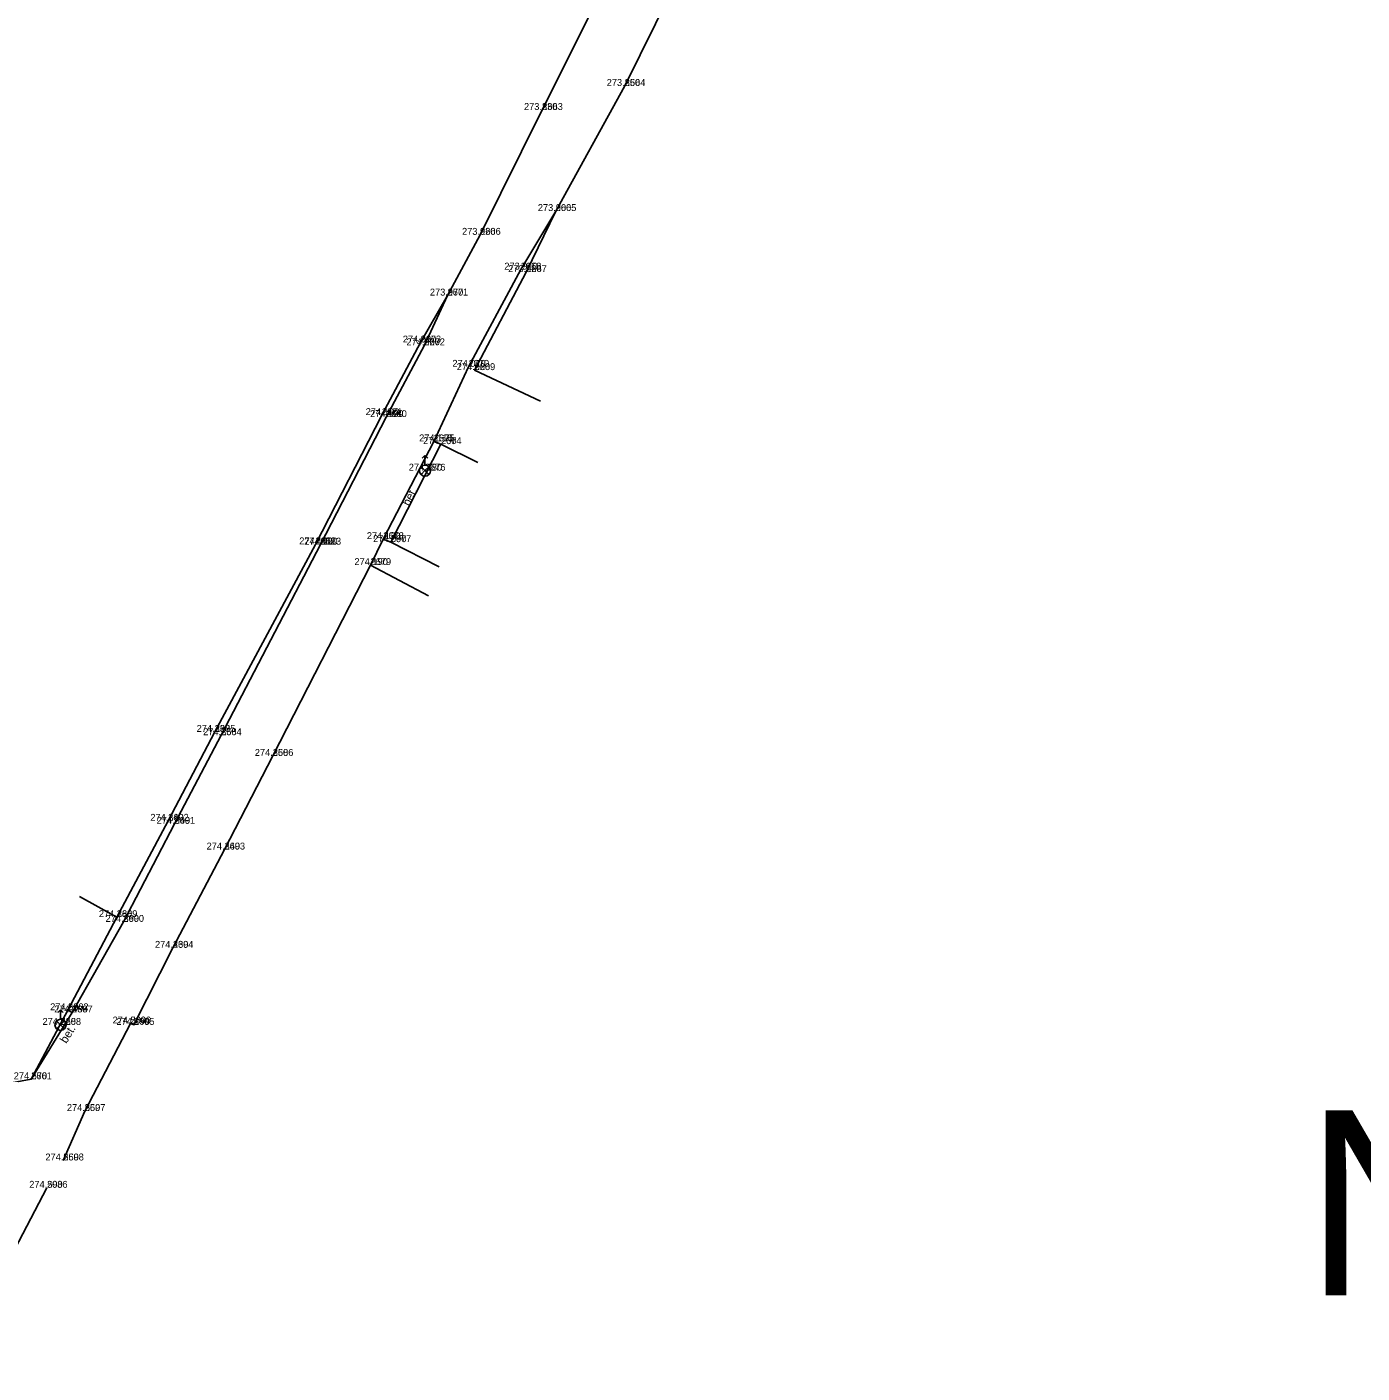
# Model space of a CAD drawing. Extents: x -776701 to -776081, y -974398 to -973771.
# Drawn here: x -776390.87 to -776342.51, y -974152.33 to -974103.58 of the extents above; entities that cross this region are included whole.
import ezdxf

# ---------------------------------------------------------------- set-up
doc = ezdxf.new("R2010")
doc.units = 0
for name, color, linetype in [('1 Body-bod', 7, 'Continuous'), ('10 Silnice-chodniky', 7, 'Continuous'), ('11 Rozhrani-nezpev zpev schody', 7, 'Continuous'), ('2 Body-cislo', 7, 'Continuous'), ('3 Body-vyska', 7, 'Continuous'), ('40 Popis-povrch', 7, 'Continuous'), ('58 Mobiliar', 7, 'Continuous'), ('7 Ploty', 7, 'Continuous'), ('Pop  PČ popisy', 7, 'Continuous')]:
    doc.layers.add(name, color=color, linetype=linetype)

msp = doc.modelspace()

# ---------------------------------------------------------------- linework, layer by layer
at = {"layer": '1 Body-bod'}
for p, q in [((-776369.21, -974105.72), (-776369.21, -974105.72)), ((-776372.2, -974106.59), (-776372.2, -974106.59)), ((-776371.71, -974110.25), (-776371.71, -974110.25)), ((-776374.45, -974111.11), (-776374.45, -974111.11)), ((-776372.98, -974112.37), (-776372.98, -974112.37)), ((-776372.78, -974112.46), (-776372.78, -974112.46)), ((-776375.63, -974113.31), (-776375.63, -974113.31)), ((-776376.61, -974115.01), (-776376.61, -974115.01)), ((-776376.47, -974115.11), (-776376.47, -974115.11)), ((-776374.87, -974115.89), (-776374.87, -974115.89)), ((-776374.65, -974116.01), (-776374.65, -974116.01)), ((-776378.01, -974117.64), (-776378.01, -974117.64)), ((-776377.85, -974117.71), (-776377.85, -974117.71)), ((-776376.13, -974118.59), (-776376.13, -974118.59)), ((-776375.87, -974118.69), (-776375.87, -974118.69)), ((-776376.45, -974119.65), (-776376.45, -974119.65)), ((-776380.42, -974122.32), (-776380.42, -974122.32)), ((-776380.23, -974122.33), (-776380.23, -974122.33)), ((-776377.96, -974122.13), (-776377.96, -974122.13)), ((-776377.69, -974122.24), (-776377.69, -974122.24)), ((-776378.42, -974123.07), (-776378.42, -974123.07)), ((-776384.06, -974129.11), (-776384.06, -974129.11)), ((-776383.83, -974129.23), (-776383.83, -974129.23)), ((-776381.96, -974129.98), (-776381.96, -974129.98)), ((-776385.75, -974132.33), (-776385.75, -974132.33)), ((-776385.52, -974132.44), (-776385.52, -974132.44)), ((-776383.71, -974133.37), (-776383.71, -974133.37)), ((-776387.61, -974135.82), (-776387.61, -974135.82)), ((-776387.37, -974135.99), (-776387.37, -974135.99)), ((-776385.58, -974136.93), (-776385.58, -974136.93)), ((-776389.38, -974139.19), (-776389.38, -974139.19)), ((-776389.23, -974139.27), (-776389.23, -974139.27)), ((-776389.65, -974139.72), (-776389.65, -974139.72)), ((-776387.12, -974139.67), (-776387.12, -974139.67)), ((-776386.99, -974139.72), (-776386.99, -974139.72)), ((-776390.71, -974141.69), (-776390.71, -974141.69)), ((-776388.77, -974142.84), (-776388.77, -974142.84)), ((-776389.55, -974144.63), (-776389.55, -974144.63)), ((-776390.14, -974145.62), (-776390.14, -974145.62))]:
    msp.add_line(p, q, dxfattribs=at)
at = {"layer": '10 Silnice-chodniky'}
for points in [[(-776371.71, -974110.25), (-776372.98, -974112.37), (-776374.87, -974115.89), (-776376.13, -974118.59), (-776377.96, -974122.13), (-776378.42, -974123.07)], [(-776375.63, -974113.31), (-776376.47, -974115.11), (-776377.85, -974117.71), (-776380.23, -974122.33), (-776383.83, -974129.23), (-776385.52, -974132.44)], [(-776375.87, -974118.69), (-776376.13, -974118.59)], [(-776377.69, -974122.24), (-776377.96, -974122.13)], [(-776390.71, -974141.69), (-776389.23, -974139.27), (-776387.37, -974135.99), (-776385.52, -974132.44)], [(-776389.38, -974139.19), (-776389.23, -974139.27)]]:
    msp.add_lwpolyline(points, dxfattribs=at)
at = {"layer": '11 Rozhrani-nezpev zpev schody'}
msp.add_lwpolyline([(-776392.71, -974139.472), (-776393.56, -974140.98), (-776391.75, -974141.88), (-776390.71, -974141.69), (-776389.38, -974139.19), (-776387.61, -974135.82), (-776388.963, -974135.076)], dxfattribs=at)
at = {"layer": '58 Mobiliar'}
for p, q in [((-776376.45, -974119.65), (-776376.593, -974119.508)), ((-776376.45, -974119.1), (-776376.55, -974119.2)), ((-776376.45, -974119.449), (-776376.45, -974119.1)), ((-776376.45, -974119.1), (-776376.35, -974119.2)), ((-776376.45, -974119.65), (-776376.307, -974119.508)), ((-776376.45, -974119.65), (-776376.593, -974119.792)), ((-776376.45, -974119.65), (-776376.45, -974119.65)), ((-776376.45, -974119.65), (-776376.307, -974119.792)), ((-776389.65, -974139.17), (-776389.75, -974139.27)), ((-776389.65, -974139.519), (-776389.65, -974139.17)), ((-776389.65, -974139.17), (-776389.55, -974139.27)), ((-776389.65, -974139.72), (-776389.792, -974139.578)), ((-776389.65, -974139.72), (-776389.792, -974139.863)), ((-776389.65, -974139.72), (-776389.508, -974139.578)), ((-776389.65, -974139.72), (-776389.65, -974139.72)), ((-776389.65, -974139.72), (-776389.508, -974139.863))]:
    msp.add_line(p, q, dxfattribs=at)
for centre in [(-776376.45, -974119.65), (-776389.65, -974139.72)]:
    msp.add_circle(centre, 0.202, dxfattribs=at)
at = {"layer": '7 Ploty'}
for points in [[(-776359.299, -974087.577), (-776360.72, -974086.96), (-776361.79, -974089.19), (-776364.38, -974095.28), (-776365.95, -974098.79), (-776367.54, -974102.33), (-776369.21, -974105.72), (-776371.71, -974110.25), (-776372.78, -974112.46), (-776374.65, -974116.01), (-776372.269, -974117.137)], [(-776369.82, -974101.8), (-776372.2, -974106.59), (-776374.45, -974111.11), (-776375.63, -974113.31), (-776376.61, -974115.01), (-776378.01, -974117.64), (-776380.42, -974122.32), (-776384.06, -974129.11), (-776385.75, -974132.33)], [(-776374.532, -974119.356), (-776375.87, -974118.69), (-776377.69, -974122.24), (-776375.94, -974123.136)], [(-776376.323, -974124.182), (-776378.42, -974123.07), (-776381.96, -974129.98), (-776383.71, -974133.37), (-776385.58, -974136.93), (-776386.99, -974139.72), (-776387.12, -974139.67), (-776388.77, -974142.84), (-776389.55, -974144.63)], [(-776387.61, -974135.82), (-776385.75, -974132.33)], [(-776393.57, -974152.33), (-776393.64, -974152.29), (-776390.14, -974145.62)]]:
    msp.add_lwpolyline(points, dxfattribs=at)

# ---------------------------------------------------------------- texts
at = {"layer": '2 Body-cislo'}
for s, p in [('2664', (-776369.21, -974105.72)), ('2663', (-776372.2, -974106.59)), ('2665', (-776371.71, -974110.25)), ('2666', (-776374.45, -974111.11)), ('2668', (-776372.98, -974112.37)), ('2667', (-776372.78, -974112.46)), ('2671', (-776375.63, -974113.31)), ('2673', (-776376.61, -974115.01)), ('2672', (-776376.47, -974115.11)), ('2670', (-776374.87, -974115.89)), ('2669', (-776374.65, -974116.01)), ('2681', (-776378.01, -974117.64)), ('2680', (-776377.85, -974117.71)), ('2675', (-776376.13, -974118.59)), ('2674', (-776375.87, -974118.69)), ('2676', (-776376.45, -974119.65)), ('2678', (-776377.96, -974122.13)), ('2682', (-776380.42, -974122.32)), ('2683', (-776380.23, -974122.33)), ('2677', (-776377.69, -974122.24)), ('2679', (-776378.42, -974123.07)), ('2685', (-776384.06, -974129.11)), ('2684', (-776383.83, -974129.23)), ('2686', (-776381.96, -974129.98)), ('2692', (-776385.75, -974132.33)), ('2691', (-776385.52, -974132.44)), ('2693', (-776383.71, -974133.37)), ('2689', (-776387.61, -974135.82)), ('2690', (-776387.37, -974135.99)), ('2694', (-776385.58, -974136.93)), ('2662', (-776389.38, -974139.19)), ('2687', (-776389.23, -974139.27)), ('2688', (-776389.65, -974139.72)), ('2696', (-776387.12, -974139.67)), ('2695', (-776386.99, -974139.72)), ('2661', (-776390.71, -974141.69)), ('2697', (-776388.77, -974142.84)), ('2698', (-776389.55, -974144.63)), ('2086', (-776390.14, -974145.62))]:
    msp.add_text(s, height=0.25, dxfattribs=at).set_placement(p)
at = {"layer": '3 Body-vyska'}
for s, p in [('273.850', (-776369.867, -974105.72)), ('273.830', (-776372.863, -974106.59)), ('273.900', (-776372.361, -974110.25)), ('273.920', (-776375.107, -974111.11)), ('273.910', (-776373.575, -974112.37)), ('273.920', (-776373.437, -974112.46)), ('273.970', (-776376.271, -974113.31)), ('274.000', (-776377.252, -974115.01)), ('274.020', (-776377.119, -974115.11)), ('274.010', (-776375.457, -974115.89)), ('274.020', (-776375.299, -974116.01)), ('274.100', (-776378.597, -974117.64)), ('274.100', (-776378.437, -974117.71)), ('274.110', (-776376.661, -974118.59)), ('274.200', (-776376.519, -974118.69)), ('274.180', (-776377.037, -974119.65)), ('274.130', (-776378.555, -974122.13)), ('274.140', (-776381.003, -974122.32)), ('274.120', (-776380.823, -974122.33)), ('274.090', (-776378.328, -974122.24)), ('274.190', (-776379.003, -974123.07)), ('274.330', (-776384.719, -974129.11)), ('274.350', (-776384.483, -974129.23)), ('274.350', (-776382.613, -974129.98)), ('274.340', (-776386.397, -974132.33)), ('274.340', (-776386.167, -974132.44)), ('274.340', (-776384.357, -974133.37)), ('274.380', (-776388.261, -974135.82)), ('274.390', (-776388.017, -974135.99)), ('274.430', (-776386.227, -974136.93)), ('274.500', (-776390.025, -974139.19)), ('274.430', (-776389.877, -974139.27)), ('274.520', (-776390.302, -974139.72)), ('274.500', (-776387.765, -974139.67)), ('274.490', (-776387.624, -974139.72)), ('274.570', (-776391.345, -974141.69)), ('274.550', (-776389.418, -974142.84)), ('274.550', (-776390.198, -974144.63)), ('274.590', (-776390.781, -974145.62))]:
    msp.add_text(s, height=0.25, dxfattribs=at).set_placement(p)
at = {"layer": '40 Popis-povrch'}
for rotation, p in [(62.8569, (-776377.022, -974120.955)), (58.5513, (-776389.438, -974140.415))]:
    msp.add_text('bet.', height=0.3, rotation=rotation, dxfattribs=at).set_placement(p)
at = {"layer": 'Pop  PČ popisy'}
msp.add_text('Novosedlice', height=6.7, dxfattribs=at).set_placement((-776344.56, -974149.52))

doc.saveas('drawing.dxf')
